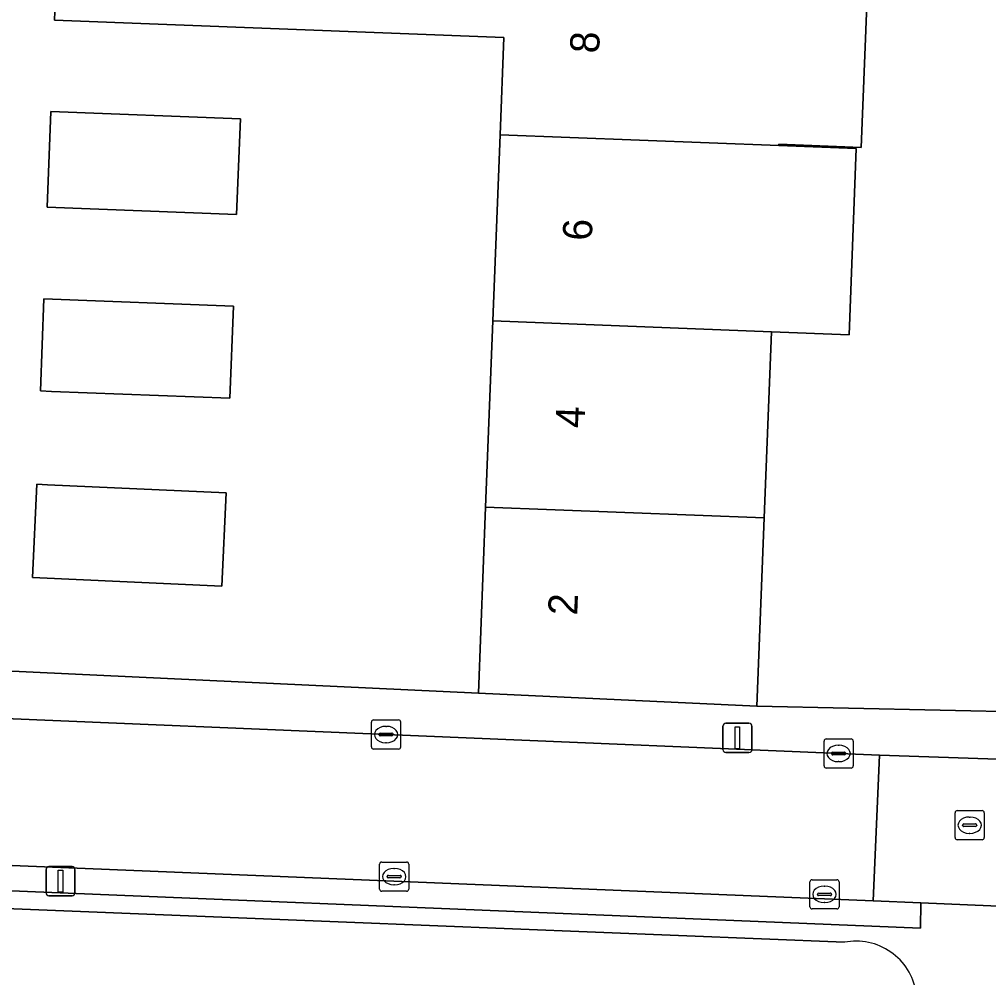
# Model space of a CAD drawing. Extents: x 160732 to 162107, y 387428 to 388479.
# Drawn here: x 161124.21 to 161157.41, y 387617.33 to 387650.15 of the extents above; entities that cross this region are included whole.
import ezdxf

# ---------------------------------------------------------------- set-up
doc = ezdxf.new("R2010")
doc.units = 0
for name, color, linetype in [('IMGEO_Erf', 7, 'Continuous'), ('IMGEO_Kolk', 7, 'Continuous'), ('IMGEO_Lichtmast', 7, 'Continuous'), ('IMGEO_Pand', 7, 'Continuous'), ('IMGEO_Pand_nummerreeks', 7, 'Continuous'), ('IMGEO_Rijbaan_lokaal_open', 7, 'Continuous'), ('IMGEO_Rioolput', 7, 'Continuous'), ('IMGEO_Voetpad_open', 7, 'Continuous')]:
    doc.layers.add(name, color=color, linetype=linetype)

msp = doc.modelspace()

# ---------------------------------------------------------------- linework, layer by layer
at = {"layer": 'IMGEO_Erf'}
for points in [[(161159.959, 387670.036), (161158.584, 387670.098), (161158.688, 387671.93), (161159.084, 387678.892), (161158.458, 387679.941), (161157.536, 387680.714), (161152.408, 387680.842), (161152.037, 387671.309), (161153.057, 387671.269), (161152.809, 387664.891), (161153.788, 387664.853), (161153.54, 387658.474), (161153.292, 387652.096), (161153.046, 387645.765), (161150.218, 387645.875), (161150.216, 387645.828), (161152.873, 387645.725), (161152.625, 387639.347), (161149.968, 387639.45), (161149.72, 387633.072), (161149.469, 387626.618), (161158.888, 387626.423)], [(161122.246, 387627.904), (161139.928, 387627.069), (161140.176, 387633.443), (161140.424, 387639.821), (161140.672, 387646.199), (161140.801, 387649.524), (161125.41, 387650.122), (161125.538, 387653.397), (161140.929, 387652.799), (161141.168, 387658.955)], [(161152.469, 387618.537), (161135.416, 387619.225), (161113.467, 387620.107)]]:
    msp.add_lwpolyline(points, dxfattribs=at)
for points in [[(161131.776, 387646.74), (161131.648, 387643.459), (161125.16, 387643.711), (161125.288, 387646.992)], [(161131.536, 387640.323), (161131.414, 387637.168), (161125.305, 387637.405), (161124.925, 387637.42), (161125.048, 387640.575)], [(161131.291, 387633.928), (161131.144, 387630.731), (161124.653, 387631.028), (161124.8, 387634.225), (161125.169, 387634.208)]]:
    msp.add_lwpolyline(points, close=True, dxfattribs=at)
msp.add_arc((161152.865, 387616.486), 2.089, 9.5377, 100.9241, dxfattribs=at)
at = {"layer": 'IMGEO_Kolk'}
for p, q in [((161136.265, 387625.226), (161136.265, 387626.078)), ((161136.34, 387626.152), (161137.192, 387626.152)), ((161136.753, 387625.932), (161136.778, 387625.932)), ((161137.266, 387626.078), (161137.266, 387625.226)), ((161136.524, 387625.646), (161136.524, 387625.658)), ((161136.962, 387625.609), (161136.564, 387625.609)), ((161136.567, 387625.695), (161136.965, 387625.695)), ((161137.008, 387625.658), (161137.008, 387625.646)), ((161151.844, 387625.503), (161152.696, 387625.503)), ((161136.776, 387625.372), (161136.751, 387625.372)), ((161151.769, 387624.577), (161151.769, 387625.429)), ((161152.257, 387625.283), (161152.282, 387625.283)), ((161152.77, 387625.429), (161152.77, 387624.577)), ((161137.192, 387625.152), (161136.34, 387625.152)), ((161152.028, 387624.997), (161152.028, 387625.009)), ((161152.466, 387624.96), (161152.068, 387624.96)), ((161152.071, 387625.046), (161152.469, 387625.046)), ((161152.512, 387625.009), (161152.512, 387624.997)), ((161152.696, 387624.503), (161151.844, 387624.503)), ((161152.28, 387624.723), (161152.255, 387624.723)), ((161136.544, 387620.359), (161136.544, 387621.211)), ((161136.619, 387621.285), (161137.471, 387621.285)), ((161137.545, 387621.211), (161137.545, 387620.359)), ((161137.032, 387621.065), (161137.057, 387621.065)), ((161136.803, 387620.779), (161136.803, 387620.791)), ((161137.241, 387620.742), (161136.843, 387620.742)), ((161136.846, 387620.828), (161137.244, 387620.828)), ((161137.287, 387620.791), (161137.287, 387620.779)), ((161151.284, 387619.751), (161151.284, 387620.603)), ((161151.359, 387620.677), (161152.211, 387620.677)), ((161152.285, 387620.603), (161152.285, 387619.751)), ((161137.471, 387620.285), (161136.619, 387620.285)), ((161137.055, 387620.505), (161137.03, 387620.505)), ((161151.543, 387620.171), (161151.543, 387620.183)), ((161151.586, 387620.22), (161151.984, 387620.22)), ((161151.772, 387620.457), (161151.797, 387620.457)), ((161152.027, 387620.183), (161152.027, 387620.171)), ((161151.981, 387620.134), (161151.583, 387620.134)), ((161151.795, 387619.897), (161151.77, 387619.897)), ((161152.211, 387619.677), (161151.359, 387619.677))]:
    msp.add_line(p, q, dxfattribs=at)
for points in [[(161136.265, 387625.226), (161136.265, 387626.078)], [(161136.34, 387626.152), (161137.192, 387626.152)], [(161137.266, 387626.078), (161137.266, 387625.226)], [(161151.844, 387625.503), (161152.696, 387625.503)], [(161151.769, 387624.577), (161151.769, 387625.429)], [(161152.77, 387625.429), (161152.77, 387624.577)], [(161137.192, 387625.152), (161136.34, 387625.152)], [(161152.696, 387624.503), (161151.844, 387624.503)], [(161136.544, 387620.359), (161136.544, 387621.211)], [(161136.619, 387621.285), (161137.471, 387621.285)], [(161137.545, 387621.211), (161137.545, 387620.359)], [(161151.284, 387619.751), (161151.284, 387620.603)], [(161151.359, 387620.677), (161152.211, 387620.677)], [(161152.285, 387620.603), (161152.285, 387619.751)], [(161137.471, 387620.285), (161136.619, 387620.285)], [(161152.211, 387619.677), (161151.359, 387619.677)]]:
    msp.add_lwpolyline(points, dxfattribs=at)
for centre, radius, start, end in [((161136.342, 387626.076), 0.0765, 91.552, 178.448), ((161136.342, 387626.076), 0.0765, 91.552, 178.448), ((161137.19, 387626.076), 0.0765, 1.552, 88.448), ((161137.19, 387626.076), 0.0765, 1.552, 88.448), ((161136.564, 387625.655), 0.0403, 85.8775, 175.7526), ((161136.561, 387625.645), 0.0366, 178.938, 274.7102), ((161136.965, 387625.652), 0.043, 264.8664, 352.4533), ((161136.969, 387625.657), 0.0386, 1.7309, 96.639), ((161151.846, 387625.427), 0.0765, 91.552, 178.448), ((161151.846, 387625.427), 0.0765, 91.552, 178.448), ((161152.694, 387625.427), 0.0765, 1.552, 88.448), ((161152.694, 387625.427), 0.0765, 1.552, 88.448), ((161136.342, 387625.228), 0.0765, 181.552, 268.448), ((161136.342, 387625.228), 0.0765, 181.552, 268.448), ((161137.19, 387625.228), 0.0765, 271.552, 358.448), ((161137.19, 387625.228), 0.0765, 271.552, 358.448), ((161152.068, 387625.006), 0.0403, 85.8775, 175.7526), ((161152.065, 387624.996), 0.0366, 178.938, 274.7102), ((161152.469, 387625.003), 0.043, 264.8664, 352.4533), ((161152.473, 387625.008), 0.0386, 1.7309, 96.639), ((161151.846, 387624.579), 0.0765, 181.552, 268.448), ((161151.846, 387624.579), 0.0765, 181.552, 268.448), ((161152.694, 387624.579), 0.0765, 271.552, 358.448), ((161152.694, 387624.579), 0.0765, 271.552, 358.448), ((161136.621, 387621.209), 0.0765, 91.552, 178.448), ((161136.621, 387621.209), 0.0765, 91.552, 178.448), ((161137.469, 387621.209), 0.0765, 1.552, 88.448), ((161137.469, 387621.209), 0.0765, 1.552, 88.448), ((161136.843, 387620.788), 0.0403, 85.8775, 175.7526), ((161136.84, 387620.778), 0.0366, 178.938, 274.7102), ((161137.244, 387620.785), 0.043, 264.8664, 352.4533), ((161137.248, 387620.79), 0.0386, 1.7309, 96.639), ((161151.361, 387620.601), 0.0765, 91.552, 178.448), ((161151.361, 387620.601), 0.0765, 91.552, 178.448), ((161152.209, 387620.601), 0.0765, 1.552, 88.448), ((161152.209, 387620.601), 0.0765, 1.552, 88.448), ((161136.621, 387620.361), 0.0765, 181.552, 268.448), ((161136.621, 387620.361), 0.0765, 181.552, 268.448), ((161137.469, 387620.361), 0.0765, 271.552, 358.448), ((161137.469, 387620.361), 0.0765, 271.552, 358.448), ((161151.583, 387620.18), 0.0403, 85.8775, 175.7526), ((161151.988, 387620.182), 0.0386, 1.7309, 96.639), ((161151.58, 387620.17), 0.0366, 178.938, 274.7102), ((161151.984, 387620.177), 0.043, 264.8664, 352.4533), ((161151.361, 387619.753), 0.0765, 181.552, 268.448), ((161151.361, 387619.753), 0.0765, 181.552, 268.448), ((161152.209, 387619.753), 0.0765, 271.552, 358.448), ((161152.209, 387619.753), 0.0765, 271.552, 358.448)]:
    msp.add_arc(centre, radius, start, end, dxfattribs=at)
for centre, major_axis, ratio, start_param, end_param in [((161136.752, 387625.652), (-0.387, 0.002), 0.722429, 4.712389, 7.853982), ((161136.777, 387625.652), (-0.39, 0.002), 0.717154, 1.570796, 4.712389), ((161152.256, 387625.003), (-0.387, 0.002), 0.722429, 4.712389, 7.853982), ((161152.281, 387625.003), (-0.39, 0.002), 0.717154, 1.570796, 4.712389), ((161137.031, 387620.785), (-0.387, 0.002), 0.722429, 4.712389, 7.853982), ((161137.056, 387620.785), (-0.39, 0.002), 0.717154, 1.570796, 4.712389), ((161151.771, 387620.177), (-0.387, 0.002), 0.722429, 4.712389, 7.853982), ((161151.796, 387620.177), (-0.39, 0.002), 0.717154, 1.570796, 4.712389)]:
    msp.add_ellipse(centre, major_axis=major_axis, ratio=ratio, start_param=start_param, end_param=end_param, dxfattribs=at)
at = {"layer": 'IMGEO_Lichtmast'}
for p, q in [((161148.308, 387625.137), (161148.308, 387625.937)), ((161148.308, 387625.937), (161148.308, 387625.137)), ((161148.408, 387626.037), (161149.198, 387626.037)), ((161149.198, 387626.037), (161148.408, 387626.037)), ((161149.298, 387625.937), (161149.298, 387625.137)), ((161149.298, 387625.137), (161149.298, 387625.937)), ((161149.198, 387625.037), (161148.408, 387625.037)), ((161148.408, 387625.037), (161149.198, 387625.037)), ((161125.118, 387620.229), (161125.118, 387621.029)), ((161125.118, 387621.029), (161125.118, 387620.229)), ((161125.218, 387621.129), (161126.008, 387621.129)), ((161126.008, 387621.129), (161125.218, 387621.129)), ((161126.108, 387621.029), (161126.108, 387620.229)), ((161126.108, 387620.229), (161126.108, 387621.029)), ((161126.008, 387620.129), (161125.218, 387620.129)), ((161125.218, 387620.129), (161126.008, 387620.129))]:
    msp.add_line(p, q, dxfattribs=at)
for points in [[(161148.728, 387625.912), (161148.878, 387625.912), (161148.878, 387625.162), (161148.728, 387625.162), (161148.728, 387625.912)], [(161125.538, 387621.004), (161125.688, 387621.004), (161125.688, 387620.254), (161125.538, 387620.254), (161125.538, 387621.004)]]:
    msp.add_lwpolyline(points, dxfattribs=at)
for centre, start, end in [((161148.408, 387625.937), 90, 180), ((161148.408, 387625.937), 90, 180), ((161149.198, 387625.937), 0, 90), ((161149.198, 387625.937), 360, 90), ((161148.408, 387625.137), 180, 270), ((161148.408, 387625.137), 180, 270), ((161149.198, 387625.137), 270, 0), ((161149.198, 387625.137), 270, 0), ((161125.218, 387621.029), 90, 180), ((161125.218, 387621.029), 90, 180), ((161126.008, 387621.029), 0, 90), ((161126.008, 387621.029), 360, 90), ((161125.218, 387620.229), 180, 270), ((161125.218, 387620.229), 180, 270), ((161126.008, 387620.229), 270, 0), ((161126.008, 387620.229), 270, 0)]:
    msp.add_arc(centre, 0.1, start, end, dxfattribs=at)
at = {"layer": 'IMGEO_Pand'}
for points in [[(161153.292, 387652.096), (161150.464, 387652.206), (161140.92, 387652.577), (161140.929, 387652.799), (161125.538, 387653.397), (161125.41, 387650.122), (161140.801, 387649.524), (161140.672, 387646.199), (161150.216, 387645.828), (161150.218, 387645.875), (161153.046, 387645.765)], [(161131.776, 387646.74), (161125.288, 387646.992), (161125.16, 387643.711), (161131.648, 387643.459)], [(161140.672, 387646.199), (161140.424, 387639.821), (161149.968, 387639.45), (161152.625, 387639.347), (161152.873, 387645.725), (161150.216, 387645.828)], [(161131.536, 387640.323), (161125.048, 387640.575), (161124.925, 387637.42), (161125.305, 387637.405), (161131.414, 387637.168)], [(161149.72, 387633.072), (161149.968, 387639.45), (161140.424, 387639.821), (161140.176, 387633.443)], [(161131.291, 387633.928), (161125.169, 387634.208), (161124.8, 387634.225), (161124.653, 387631.028), (161131.144, 387630.731)], [(161139.928, 387627.069), (161149.469, 387626.618), (161149.72, 387633.072), (161140.176, 387633.443)]]:
    msp.add_lwpolyline(points, close=True, dxfattribs=at)
at = {"layer": 'IMGEO_Rijbaan_lokaal_open'}
msp.add_lwpolyline([(161114.477, 387621.556), (161153.452, 387619.956), (161153.669, 387624.945), (161122.071, 387626.266)], dxfattribs=at)
msp.add_lwpolyline([(161155.08, 387619.892), (161159.879, 387619.683), (161160.07, 387624.724), (161153.669, 387624.945), (161153.452, 387619.956)], close=True, dxfattribs=at)
at = {"layer": 'IMGEO_Rioolput'}
for p, q in [((161156.257, 387622.12), (161156.257, 387622.972)), ((161156.332, 387623.046), (161157.184, 387623.046)), ((161157.258, 387622.972), (161157.258, 387622.12)), ((161156.516, 387622.54), (161156.516, 387622.552)), ((161156.559, 387622.589), (161156.957, 387622.589)), ((161156.745, 387622.826), (161156.77, 387622.826)), ((161157, 387622.552), (161157, 387622.54)), ((161156.954, 387622.503), (161156.556, 387622.503)), ((161156.768, 387622.266), (161156.743, 387622.266)), ((161157.184, 387622.046), (161156.332, 387622.046))]:
    msp.add_line(p, q, dxfattribs=at)
for points in [[(161156.257, 387622.12), (161156.257, 387622.972)], [(161156.332, 387623.046), (161157.184, 387623.046)], [(161157.258, 387622.972), (161157.258, 387622.12)], [(161157.184, 387622.046), (161156.332, 387622.046)]]:
    msp.add_lwpolyline(points, dxfattribs=at)
for centre, radius, start, end in [((161156.334, 387622.97), 0.0765, 91.552, 178.448), ((161156.334, 387622.97), 0.0765, 91.552, 178.448), ((161157.182, 387622.97), 0.0765, 1.552, 88.448), ((161157.182, 387622.97), 0.0765, 1.552, 88.448), ((161156.556, 387622.549), 0.0403, 85.8775, 175.7526), ((161156.553, 387622.539), 0.0366, 178.938, 274.7102), ((161156.957, 387622.546), 0.043, 264.8664, 352.4533), ((161156.961, 387622.551), 0.0386, 1.7309, 96.639), ((161156.334, 387622.122), 0.0765, 181.552, 268.448), ((161156.334, 387622.122), 0.0765, 181.552, 268.448), ((161157.182, 387622.122), 0.0765, 271.552, 358.448), ((161157.182, 387622.122), 0.0765, 271.552, 358.448)]:
    msp.add_arc(centre, radius, start, end, dxfattribs=at)
for centre, major_axis, ratio, start_param, end_param in [((161156.744, 387622.546), (-0.387, 0.002), 0.722429, 4.712389, 7.853982), ((161156.769, 387622.546), (-0.39, 0.002), 0.717154, 1.570796, 4.712389)]:
    msp.add_ellipse(centre, major_axis=major_axis, ratio=ratio, start_param=start_param, end_param=end_param, dxfattribs=at)
at = {"layer": 'IMGEO_Voetpad_open'}
for points in [[(161163.888, 387626.006), (161158.888, 387626.423), (161149.469, 387626.618), (161139.928, 387627.069), (161122.246, 387627.904)], [(161122.071, 387626.266), (161153.669, 387624.945), (161160.07, 387624.724), (161189.162, 387623.521)], [(161113.348, 387620.734), (161155.07, 387619.021), (161155.08, 387619.892), (161153.452, 387619.956), (161114.477, 387621.556)], [(161159.879, 387619.683), (161155.08, 387619.892), (161155.07, 387619.021), (161113.348, 387620.734)], [(161113.467, 387620.107), (161135.416, 387619.225), (161152.469, 387618.537)]]:
    msp.add_lwpolyline(points, dxfattribs=at)
msp.add_arc((161152.865, 387616.486), 2.089, 9.5377, 100.9241, dxfattribs=at)

# ---------------------------------------------------------------- texts
at = {"layer": 'IMGEO_Pand_nummerreeks'}
for s, rotation, p in [('8', 87.7714, (161144.062, 387648.973)), ('6', 87.773, (161143.813, 387642.554)), ('4', 87.773, (161143.563, 387636.138)), ('2', 87.773, (161143.314, 387629.72))]:
    msp.add_text(s, height=1, rotation=rotation, dxfattribs=at).set_placement(p)

doc.saveas('drawing.dxf')
